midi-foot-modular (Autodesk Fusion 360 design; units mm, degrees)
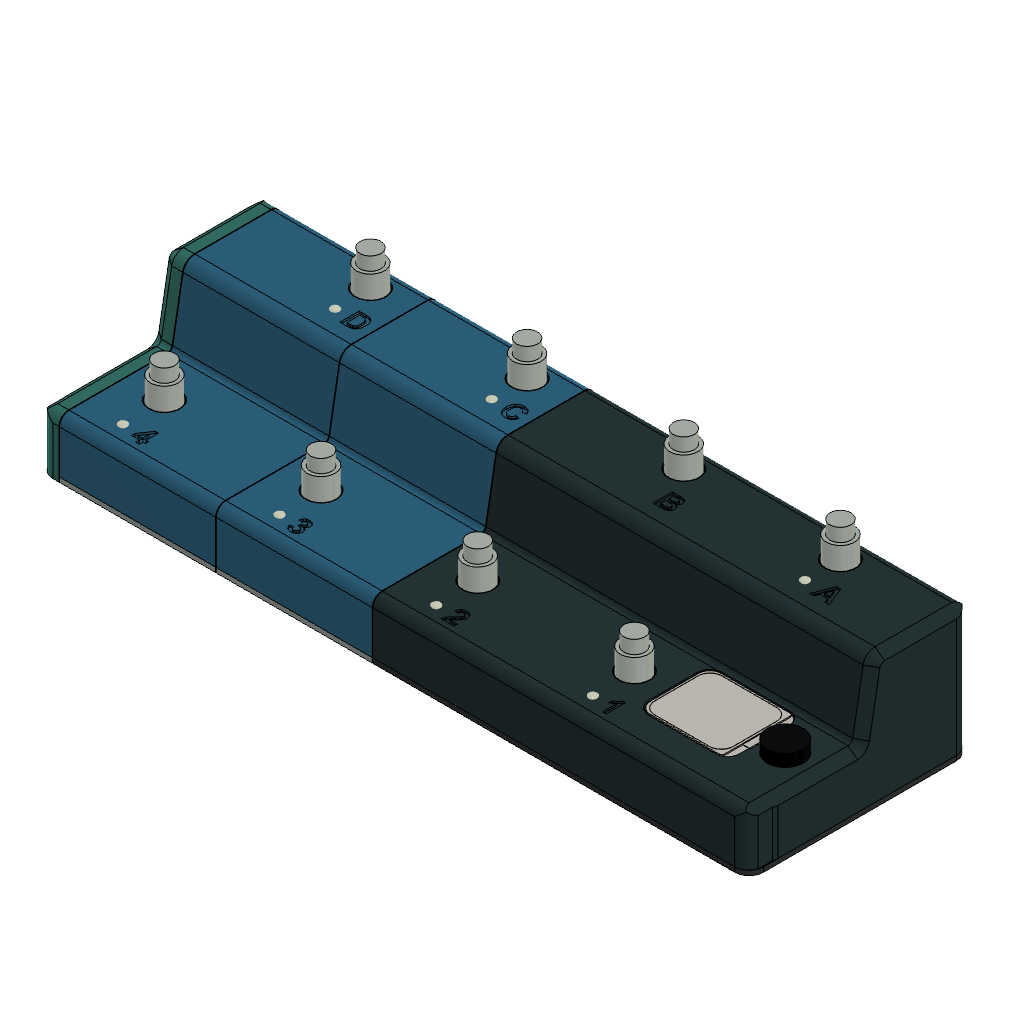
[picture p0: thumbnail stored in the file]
named bodies: "M2x6 pair base 1", "M2x6 pair base 2", "Actual 30x13x15 body (1) (1) (1)", "Mount barrel and shaft - protrusion increased 5mm (1)", "8.7mm actuator cap - raised 5mm (1)", "Actual 30x13x15 body (1) (1) (1) - front row offset 8mm", "Mount barrel and shaft - protrusion increased 5mm (1) - front row offset 8mm", "8.7mm actuator cap - raised 5mm (1) - front row offset 8mm", "5mm lens - reference 6mm flange and 8.7mm body - recessed 4.9mm", "DIN - reference 0.5mm lead, trimmed to 6mm - recessed 4.9mm", "5V - reference 0.5mm lead, trimmed to 6mm - recessed 4.9mm", "GND - reference 0.5mm lead, trimmed to 6mm - recessed 4.9mm", "DOUT - reference 0.5mm lead, trimmed to 6mm - recessed 4.9mm", "5mm lens - reference 6mm flange and 8.7mm body - recessed 4.9mm (1)", "DIN - reference 0.5mm lead, trimmed to 6mm - recessed 4.9mm (1)", "5V - reference 0.5mm lead, trimmed to 6mm - recessed 4.9mm (1)", "GND - reference 0.5mm lead, trimmed to 6mm - recessed 4.9mm (1)", "DOUT - reference 0.5mm lead, trimmed to 6mm - recessed 4.9mm (1)", "M2x6 base screw 3", "M2x6 extra right base rear near split X201", "M2x6 extra right base front near split X201", "Actual 30x13x15 body (1) (1) (1) (1)", "Mount barrel and shaft - protrusion increased 5mm (1) (1)", "8.7mm actuator cap - raised 5mm (1) (1)", "Actual 30x13x15 body (1) (1) (1) (2)", "Mount barrel and shaft - protrusion increased 5mm (1) (2)", "8.7mm actuator cap - raised 5mm (1) (2)", "Actual 30x13x15 body (1) (1) (1) - front row offset 8mm (1)", "Mount barrel and shaft - protrusion increased 5mm (1) - front row offset 8mm (1)", "8.7mm actuator cap - raised 5mm (1) - front row offset 8mm (1)", "Actual 30x13x15 body (1) (1) (1) - front row offset 8mm (2)", "Mount barrel and shaft - protrusion increased 5mm (1) - front row offset 8mm (2)", "8.7mm actuator cap - raised 5mm (1) - front row offset 8mm (2)", "DIN - reference 0.5mm lead, trimmed to 6mm - recessed 4.9mm (2)", "5V - reference 0.5mm lead, trimmed to 6mm - recessed 4.9mm (2)", "GND - reference 0.5mm lead, trimmed to 6mm - recessed 4.9mm (2)", "DOUT - reference 0.5mm lead, trimmed to 6mm - recessed 4.9mm (2)", "5mm lens - reference 6mm flange and 8.7mm body - recessed 4.9mm (2)", "5mm lens - reference 6mm flange and 8.7mm body - recessed 4.9mm (3)", "DIN - reference 0.5mm lead, trimmed to 6mm - recessed 4.9mm (3)", "5V - reference 0.5mm lead, trimmed to 6mm - recessed 4.9mm (3)", "GND - reference 0.5mm lead, trimmed to 6mm - recessed 4.9mm (3)", "DOUT - reference 0.5mm lead, trimmed to 6mm - recessed 4.9mm (3)", "5mm lens - reference 6mm flange and 8.7mm body - recessed 4.9mm (4)", "DIN - reference 0.5mm lead, trimmed to 6mm - recessed 4.9mm (4)", "5V - reference 0.5mm lead, trimmed to 6mm - recessed 4.9mm (4)", "GND - reference 0.5mm lead, trimmed to 6mm - recessed 4.9mm (4)", "DOUT - reference 0.5mm lead, trimmed to 6mm - recessed 4.9mm (4)", "5mm lens - reference 6mm flange and 8.7mm body - recessed 4.9mm (5)", "DIN - reference 0.5mm lead, trimmed to 6mm - recessed 4.9mm (5)", "5V - reference 0.5mm lead, trimmed to 6mm - recessed 4.9mm (5)", "GND - reference 0.5mm lead, trimmed to 6mm - recessed 4.9mm (5)", "DOUT - reference 0.5mm lead, trimmed to 6mm - recessed 4.9mm (5)", "Exact Pololu 4083 double-sided assembly", "M8 threaded barrel - 8mm long - no helix", "Rear flange/body - 4mm long - assumed diameter 12mm", "2.1mm center contact - nominal visual geometry", "2mm nut - conservative 13mm AF envelope", "Center-negative solder lug - nominal location", "Positive sleeve solder lug - nominal location"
